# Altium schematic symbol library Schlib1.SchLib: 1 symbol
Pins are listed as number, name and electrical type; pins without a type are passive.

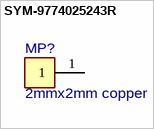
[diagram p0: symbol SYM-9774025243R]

## SYM-9774025243R
designator MP?, comment 2mmx2mm copper
Spacer, SMT, Swage Round, Steel, 2x2mm; PartNumber: 2mmx2mmx2mm
footprint Copper 2x2 (copper 2mmx2mmx2mm)
pins: 1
